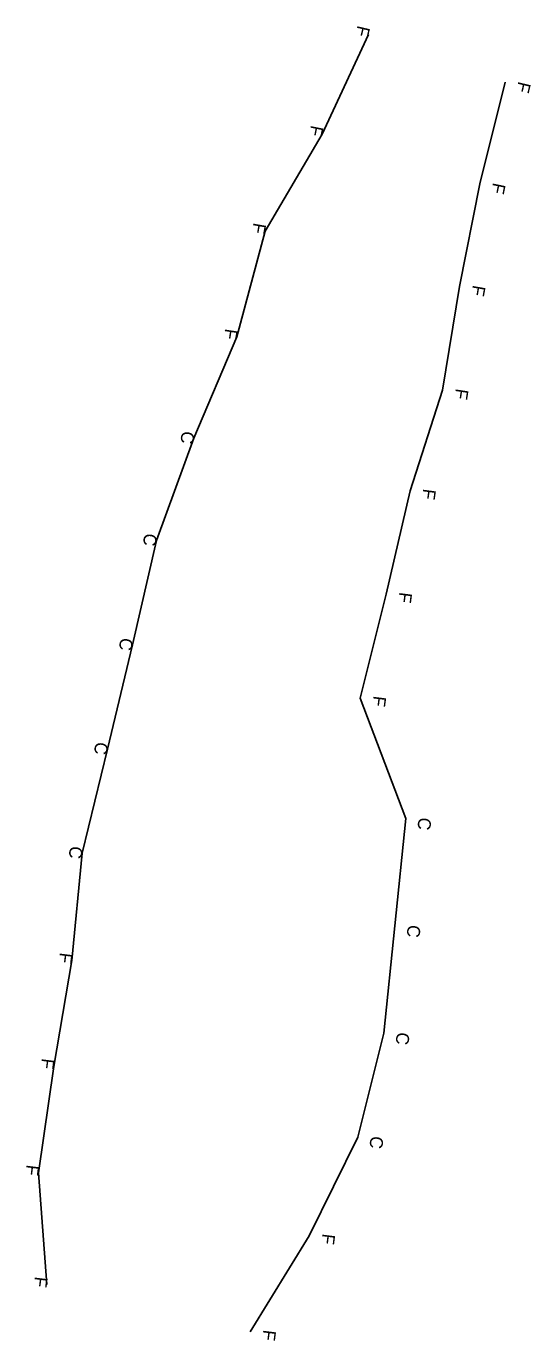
# Model space of a CAD drawing. Extents: x -26 to 2348536, y -510 to 844755.
# Drawn here: x 2348301 to 2348536, y 844141 to 844755 of the extents above; entities that cross this region are included whole.
import ezdxf

# ---------------------------------------------------------------- set-up
doc = ezdxf.new("R2010")
doc.units = 0
for name, color, linetype in [('Prop SS Cut Line', 7, 'Continuous'), ('Prop SS Cut Text', 7, 'Continuous'), ('Prop SS Fill Line', 7, 'Continuous'), ('Prop SS Fill Text', 7, 'Continuous'), ('Prop SS Transition Line', 7, 'Continuous')]:
    doc.layers.add(name, color=color, linetype=linetype)

msp = doc.modelspace()

# ---------------------------------------------------------------- linework, layer by layer
at = {"layer": 'Prop SS Cut Line'}
for p, q in [((2348378.96, 844562.69), (2348361.5, 844514.98)), ((2348361.5, 844514.98), (2348350.31, 844466.16)), ((2348350.31, 844466.16), (2348338.67, 844417.53)), ((2348338.67, 844417.53), (2348326.86, 844368.94)), ((2348477.78, 844385.07), (2348472.79, 844334.9)), ((2348472.79, 844334.9), (2348467.63, 844284.76)), ((2348467.63, 844284.76), (2348455.43, 844236.26))]:
    msp.add_line(p, q, dxfattribs=at)
at = {"layer": 'Prop SS Fill Line'}
for p, q in [((2348460.48, 844751.19), (2348438.85, 844704.73)), ((2348524.13, 844729.01), (2348512.34, 844681.52)), ((2348438.85, 844704.73), (2348412.17, 844659.33)), ((2348512.34, 844681.52), (2348502.95, 844633.51)), ((2348412.17, 844659.33), (2348399.03, 844610)), ((2348502.95, 844633.51), (2348495.01, 844585.05)), ((2348495.01, 844585.05), (2348479.82, 844538.13)), ((2348479.82, 844538.13), (2348468.7, 844489.81)), ((2348468.7, 844489.81), (2348456.62, 844441.35)), ((2348322.06, 844318.72), (2348313.67, 844269.34)), ((2348313.67, 844269.34), (2348306.54, 844219.66)), ((2348306.54, 844219.66), (2348310.41, 844167.41)), ((2348432.82, 844190.19), (2348405.26, 844145.28))]:
    msp.add_line(p, q, dxfattribs=at)
at = {"layer": 'Prop SS Transition Line'}
for p, q in [((2348399.03, 844610), (2348378.96, 844562.69)), ((2348456.62, 844441.35), (2348477.78, 844385.07)), ((2348326.86, 844368.94), (2348322.06, 844318.72)), ((2348455.43, 844236.26), (2348432.82, 844190.19))]:
    msp.add_line(p, q, dxfattribs=at)

# ---------------------------------------------------------------- texts
at = {"layer": 'Prop SS Cut Text'}
for s, rotation, p in [('F', 256.78421, (2348530.38, 844729.56)), ('F', 258.46937, (2348518.58, 844682.26)), ('F', 260.12014, (2348509.17, 844634.43)), ('F', 261.42662, (2348501.2, 844586.11)), ('F', 262.31495, (2348486, 844539.29)), ('F', 262.78512, (2348474.87, 844491.01)), ('F', 262.86664, (2348462.79, 844442.57)), ('C', 262.86664, (2348483.89, 844385.82)), ('C', 262.86664, (2348478.89, 844335.64)), ('C', 262.86664, (2348473.74, 844285.5)), ('C', 262.86664, (2348461.53, 844237.01)), ('F', 262.86664, (2348438.99, 844191.41)), ('F', 262.86664, (2348411.42, 844146.5))]:
    msp.add_text(s, height=6, rotation=rotation, dxfattribs=at).set_placement(p)
at = {"layer": 'Prop SS Fill Text'}
for s, rotation, p in [('F', 256.78421, (2348455.41, 844755.7)), ('F', 258.46937, (2348433.65, 844709.09)), ('F', 260.12014, (2348406.85, 844663.54)), ('F', 261.42662, (2348393.61, 844614.08)), ('C', 262.31495, (2348373.42, 844566.22)), ('C', 262.78512, (2348355.93, 844518.46)), ('C', 262.86664, (2348344.73, 844469.63)), ('C', 262.86664, (2348333.09, 844421.01)), ('C', 262.86664, (2348321.28, 844372.42)), ('F', 262.86664, (2348316.54, 844322.66)), ('F', 262.86664, (2348308.15, 844273.28)), ('F', 262.86664, (2348301.02, 844223.6)), ('F', 262.86664, (2348304.89, 844171.35))]:
    msp.add_text(s, height=6, rotation=rotation, dxfattribs=at).set_placement(p)

doc.saveas('drawing.dxf')
